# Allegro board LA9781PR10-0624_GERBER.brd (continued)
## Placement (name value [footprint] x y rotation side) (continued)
CD74  -  [C_0603]  151.74 45.85 270 bottom
CD75  -  [C_0603]  153.39 45.85 270 bottom
CD76  -  [C_0603]  157.45 45.85 270 bottom
CD77  -  [C_0603]  158.85 45.85 270 bottom
CD78  -  [C_0603]  162.79 45.85 270 bottom
CD79  -  [C_0603]  164.06 45.85 270 bottom
CD80  -  [C_SX]  179.04 84.27 0 top
CD81  -  [C_0402]  119.18 54.04 180 bottom
CD82  -  [C_0402]  119.18 53.15 180 bottom
CD83  -  [C_0402]  119.18 52.26 180 bottom
CD84  -  [C_0402]  119.18 51.37 180 bottom
CD85  -  [C_0402]  148.56 45.86 270 bottom
CD86  -  [C_0402]  147.55 45.86 270 bottom
CD87  -  [C_0402]  128.41 46.11 270 bottom
CD88  -  [C_0402]  127.52 46.11 270 bottom
CD89  -  [C_0402]  172.19 45.71 90 top
CD90  -  [C_0402]  144.58 83.63 180 top
CD91  -  [C_0402]  167.99 44.31 90 top
CD92  -  [C_0402]  209.9 89.9 90 top
CE1  -  [C_0402]  99.85 64.83 0 bottom
CE2  -  [C_0402]  100.73 57.6 0 bottom
CE3  -  [C_0402]  247.42 59.75 0 bottom
CE6  -  [C_0805]  125.58 113.56 270 bottom
CE8  -  [C_0402]  103.86 113.4 90 bottom
CE9  -  [C_0402]  100.81 113.4 90 bottom
CH2  -  [C_0402]  41.2 85.54 180 bottom
CH4  -  [C_0402]  65 55.89 270 top
CH5  -  [C_0402]  65 58.05 270 top
CH6  -  [C_0402]  68.53 54.14 90 top
CH7  -  [C_0402]  66.9 56.78 270 top
CH9  -  [C_0402]  79.98 52.77 270 bottom
CH10  -  [C_0402]  63.42 84.9 180 bottom
CH11  -  [C_0402]  63.55 48.32 180 top
CH12  -  [C_0402]  54.96 77.15 90 top
CH13  -  [C_0402]  89.92 73.01 0 bottom
CH14  -  [C_0402]  93.6 74.81 270 bottom
CH15  -  [C_0402]  87.98 59.75 0 top
CH16  -  [C_0402]  88.04 61.02 0 top
CH17  -  [C_0402]  62.28 78.68 180 bottom
CH18  -  [C_0402]  88.24 63.44 270 top
CH19  -  [C_0402]  86.21 62.8 270 top
CH20  -  [C_0603]  89.38 63.39 270 top
CH21  -  [C_0603]  75.03 76.26 90 top
CH22  -  [C_0402]  77.05 72.49 90 top
CH23  -  [C_0402]  74.64 71.05 270 top
CH24  -  [C_0402]  76.1 71.07 270 top
CH25  -  [C_0402]  76.1 68.32 270 top
CH26  -  [C_0603]  86.2 76.31 0 top
CH27  -  [C_0402]  79.34 64.7 270 top
CH28  -  [C_0805]  83.76 81.6 180 top
CH29  -  [C_0402]  76.1 63.85 90 top
CH30  -  [C_0402]  74.65 65.82 270 top
CH31  -  [C_0603]  76.81 76.96 270 top
CH32  -  [C_0603]  76.42 83.55 90 top
CH33  -  [C_0603]  74.7 83.55 90 top
CH34  -  [C_0402]  74.64 69.29 270 top
CH35  -  [C_0402]  79.34 65.57 90 top
CH36  -  [C_0402]  82.47 73.02 270 top
CH37  -  [C_0402]  77.93 69.3 90 top
CH38  -  [C_0603]  94.65 76.45 90 bottom
CH39  -  [C_0402]  73.1 66.82 270 top
CH40  -  [C_0402]  67.56 66.64 0 top
CH41  -  [C_0603]  81.76 75.95 90 top
CH42  -  [C_0402]  79.4 70.42 270 top
CH43  -  [C_0402]  76.1 65.63 90 top
CH44  -  [C_0402]  75.23 55.11 270 bottom
CH45  -  [C_0402]  77.75 66.27 90 top
CH46  -  [C_0402]  72.24 67.83 180 top
CH47  -  [C_0402]  85.83 65.6 90 top
CH48  -  [C_0402]  76.99 62.71 90 top
CH49  -  [C_0402]  73.07 69.99 90 top
CH50  -  [C_0402]  77.06 71.01 270 top
CH51  -  [C_0402]  79.6 55.82 90 top
CH52  -  [C_0603]  75.71 84.37 90 bottom
CH53  -  [C_0402]  69.26 62.42 90 top
CH54  -  [C_0402]  74.45 64.1 270 top
CH55  -  [C_0402]  71.22 52.77 270 bottom
CH56  -  [C_0402]  72.11 52.77 270 bottom
CH57  -  [C_0402]  73 52.77 270 bottom
CH58  -  [C_0402]  84.94 66.99 90 top
CH59  -  [C_0402]  73.07 68.19 90 top
CH60  -  [C_SX]  48.87 64.83 180 bottom
CH63  -  [C_0603]  90.67 76.47 90 bottom
CH64  -  [C_0402]  90.07 75.42 0 bottom
CH65  -  [C_0402]  81.13 70.17 90 top
CH66  -  [C_0402]  77.44 55.18 90 top
CH67  -  [C_0402]  80.93 68.51 270 top
CH68  -  [C_0402]  86.83 68.55 90 top
CH69  -  [C_0402]  79.4 67.35 90 top
CH70  -  [C_0402]  85.94 68.55 90 top
CH71  -  [C_0402]  81.93 67.87 0 top
CH72  -  [C_0402]  80.93 65.39 90 top
CH73  -  [C_0402]  77.88 63.73 90 top
CH74  -  [C_0402]  81.08 64.55 270 top
CH75  -  [C_0402]  80.49 59.5 180 top
CH76  -  [C_0402]  87.98 58.36 0 top
CH77  -  [C_0402]  92.56 56.58 0 bottom
CH78  -  [C_0402]  90.19 57.72 0 bottom
CH79  -  [C_0402]  88.95 54.93 180 top
CH80  -  [C_0402]  87.98 57.09 0 top
CH81  -  [C_0402]  68.43 71.51 270 top
CH82  -  [C_0402]  67.52 71.53 270 top
CH83  -  [C_0402]  66.65 71.51 270 top
CMOS1  -  [SHORTPADS]  68.93 56.58 270 top
D6  -  [BAT54CW_SOT323-3]  92.34 163.64 90 bottom
D7  -  [RB751VM-40TE-17_SOD323-2]  118.34 129.57 90 top
D8  -  [RB751VM-40TE-17_SOD323-2]  123.04 129.57 90 top
D14  -  [TVWDF1004AD0_DFN9]  290.15 112.29 180 bottom
D15  -  [L30ESDL5V0C3-2_SOT23-3]  296.77 122.01 0 bottom
D16  -  [TVWDF1004AD0_DFN9]  288.44 98.3 90 top
D17  -  [L30ESDL5V0C3-2_SOT23-3]  283.06 95 270 bottom
D18  -  [RB751VM-40TE-17_SOD323-2]  120.37 129.57 90 top
D19  -  [RB751VM-40TE-17_SOD323-2]  115.29 131.54 270 top
D28  -  [RB751S40T1_SOD523-2]  298.04 110.37 270 bottom
D31  -  [RB751V40_SC76-2]  119.99 155.05 90 bottom
D32  -  [RB751S40T1_SOD523-2]  120.43 131.2 0 bottom
D33  -  [L30ESD24VC3-2_SOT23-3]  121.39 111.42 180 bottom
D35  -  [RB751V40_SC76-2]  126.97 155.17 90 bottom
D36  -  [RB751V40_SC76-2]  136.07 171.39 180 top
D53  -  [RB751VM-40TE-17_SOD323-2]  93.79 164.53 0 bottom
D59  -  [RB751S40T1_SOD523-2]  33.5 85.98 270 top
D62  -  [RB751S40T1_SOD523-2]  34.9 85.98 270 top
D64  -  [RB751VM-40TE-17_SOD323-2]  100.18 162.08 90 bottom
D65  -  [RB751V40_SC76-2]  101.83 162.03 90 bottom
D66  -  [RB751VM-40TE-17_SOD323-2]  101.9 165.64 90 bottom
D68  -  [RB751VM-40TE-17_SOD323-2]  100.25 165.64 90 bottom
D69  -  [RB751VM-40TE-17_SOD323-2]  98.53 162.08 90 bottom
D71  -  [RB751VM-40TE-17_SOD323-2]  98.6 165.64 90 bottom
D73  -  [L30ESDL5V0C3-2_SOT23-3]  15.34 166.97 180 top
D90  -  [RB751S40T1_SOD523-2]  14.64 84.9 180 bottom
D91  -  [BAT1000-7-F_SOT23-3]  286.88 144.21 180 top
F3  -  [F_1206L150THWR]  290.49 141.4 90 top
FD1  -  [FIDUCIAL_C40M80]  12.67 161.86 0 top
FD2  -  [FIDUCIAL_C40M80]  10.64 161.99 180 bottom
FD3  -  [FIDUCIAL_C40M80]  290.55 14.03 0 top
FD4  -  [FIDUCIAL_C40M80]  290.55 14.03 180 bottom
H1  -  [H_3P0]  3.49 162.2 0 top
H2  -  [H_3P8]  33.69 75.9 0 top
H3  -  [H_3P0]  30.49 16.2 0 top
H4  -  [H_12P0X7P5]  48.39 32.2 180 top
H5  -  [H_3P0]  69.49 167.7 0 top
H6  -  [H_3P0]  141.69 146 0 top
H7  -  [H_3P8]  108.69 75.9 0 top
H8  -  [H_3P0]  117.49 77.2 0 top
H9  -  [H_3P0]  115.89 12.23 0 top
H10  -  [H_3P0]  123.29 7.43 0 top
H11  -  [H_3P0]  195.29 169.2 0 top
H12  -  [H_4P2]  151.67 144.99 0 top
H13  -  [H_4P2]  208.41 141.51 0 top
H14  -  [H_4P2]  149.69 104.2 0 top
H15  -  [H_4P2]  210.8 99.57 0 top
H16  -  [H_3P0]  215.49 90.5 0 top
H17  -  [H_3P6]  220.49 77.8 0 top
H18  -  [H_3P0]  198.39 26.03 0 top
H19  -  [H_3P6]  220.49 16.1 0 top
H20  -  [H_3P0]  270.89 87.13 0 top
H21  -  [H_3P0]  296.49 169.7 0 top
H22  -  [H_3P6X3P0]  293.29 159.2 0 top
H23  -  [H_3P6]  297.09 77.8 0 top
H24  -  [H_3P6]  297.09 16.1 0 top
H25  -  [H_3P0]  289.89 7.03 0 top
H26  -  [H_1P2]  73.09 157.9 0 top
H27  -  [H_1P2]  104.84 157.9 0 top
H28  -  [H_1P2]  136.59 157.9 0 top
JAPS1  -  [TYCO_1-2041070-6_16P]  14.09 120.44 270 bottom
JBT1  -  [ACES_50228-0127N-001_12P]  302.56 106.44 0 top
JCAM1  -  [ACES_50238-0207N-002_20P]  13.18 121.35 135 top
JCPU1  -  [INTEL_HASWELL_947P-T]  161.59 104.84 0 top
JCRT1  -  [SUYIN_070449HR015M221ZR_15P]  81.55 173.96 0 top
JDEG2  -  [ACES_87152-10071_10P]  275.84 31.09 270 bottom
JDIMM1  -  [TYCO_2-2013310-1_204P]  189.24 72.25 0 top
JDIMM2  -  [TYCO_2-2013289-1_204P]  189.24 64.05 0 bottom
JDIMM3  -  [TYCO_2-2013289-1_204P]  189.24 58.05 0 top
JDIMM4  -  [TYCO_2-2013290-1_204P]  189.24 49.85 0 bottom
JDOCK1  -  [JAE_WD2F144WB5R400_144P]  81.74 118.7 0 bottom
JDP1  -  [FOX_3V11211-NBYD7-7H_20P]  293.78 150.25 90 top
JEDP1  -  [ACES_50398-04071-001_40P]  130.49 156.27 0 top
JESA1  -  [TAIWI_EU093-117CRL-TW_11P]  14.49 170.97 180 top
JFAN1  -  [ACES_50271-0040N-001_4P]  226.23 80.15 315 bottom
JFAN2  -  [ACES_50271-0040N-001_4P]  11.15 87.44 90 bottom
JHDMI1  -  [CONCR_099AAAC19BBLCNF_19P]  27.94 168.64 180 top
JIO1  -  [FOX_QTSA1401-7011-9H_140P-T]  14.14 102.9 90 top
JKB1  -  [E-T_6900K-G10N-40R_10P]  131.5 103.62 0 top
JLOM1  -  [SANTA_130454-H_13P]  52.22 162.27 180 top
JLVDS1  -  [ACES_50398-04071-001_40P]  98.74 156.27 0 top
JMINI1  -  [LCN_DAN08-52526-0100_52P]  269.69 65 270 bottom
JMINI2  -  [LCN_DAN08-52526-0100_52P]  110.69 168 0 bottom
JMINI3  -  [LCN_DAN08-52526-0100_52P]  90.54 20.35 180 bottom
JMINI4  -  [LCN_DAN08-52526-0100_52P]  9.64 157.75 0 bottom
JMXM1  -  [JAE_MM70-314-310B1-1-R3_310P-S]  31.19 136.7 0 top
JODD1  -  [OCTEK_SLS-13SZAB_13P]  24.26 41.63 270 top
JPB1  -  [ACES_50228-0067N-001_6P]  276.49 90.98 180 top
JRTC1  -  [ACES_50271-0020N-001_2P]  51.89 99.82 270 bottom
JSATA1  -  [OCTEK_SAT-22PDAB_22P]  200.43 35.91 90 top
JSATA2  -  [OCTEK_SAT-22PDAB_22P]  63.98 32.2 0 top
JSIM1  -  [T-SOL_159-1000302602_10P-T]  263.44 19.03 180 bottom
JSPI1  -  [TYCO_2-2041070-0_20P-T]  111.53 50.74 0 bottom
JTAG1  -  [SHORTPADS]  251.43 38.04 0 bottom
JUSB1  -  [LOTES_AUSB0041-P002A_9P]  293.26 116.34 90 top
JUSB2  -  [LOTES_AUSB0041-P002A_9P]  293.26 93.25 90 top
JUSH1  -  [E-T_6700K-Y20N-00L_20P]  114.91 36.82 90 top
JWL1  -  [ACES_50228-0034N-001_3P]  283.62 7.24 180 top
JXDP1  -  [ACES_50559-02601-001_26P-T]  207.99 128.44 270 top
JXDP2  -  [SAMTE_BSH-030-01-L-D-A_60P]  43.63 74.95 90 bottom
L1  -  [MURAT_BLM15BB470SN1D_2P]  80.11 160.72 180 bottom
L2  -  [MURAT_BLM15BB470SN1D_2P]  86.59 161.06 90 bottom
L3  -  [MURAT_BLM15BB470SN1D_2P]  88.49 161.01 90 bottom
L4  -  [MURAT_BLM15AG121SN1D_L0402_2P]  86.11 165.42 0 top
L5  -  [MURAT_BLM15AG121SN1D_L0402_2P]  89.73 165.42 180 top
L10  -  [MURAT_DLW21SN121SQ2L_4P]  31.62 127.5 180 top
L11  -  [MURAT_DLW21SN121SQ2L_4P]  31.53 115.32 180 top
L19  -  [MURAT_DLW21SN900HQ2L_0805_4P]  36.59 162.92 90 top
L23  -  [MURAT_DLW21SN900HQ2L_0805_4P]  33.04 162.92 90 top
L24  -  [MURAT_DLW21SN900HQ2L_0805_4P]  29.48 162.92 90 top
L25  -  [MURAT_DLW21SN900HQ2L_0805_4P]  26.18 162.92 90 top
L29  -  [TAIYO_CBC2012T4R7M_2P]  107.29 85.55 90 bottom
L39  -  [MURAT_DLW21SN900SQ2L_0805_4P]  297.2 117.75 270 bottom
L40  -  [MURAT_DLW21SN900HQ2L_0805_4P]  288.56 110.39 270 bottom
L41  -  [CHENG_OCE2012120YZF_4P]  278.09 90.28 270 bottom
L42  -  [MURAT_DLW21SN900HQ2L_0805_4P]  290.59 110.39 270 bottom
L43  -  [MURAT_DLW21SN900HQ2L_0805_4P]  285.02 100.08 180 top
L44  -  [MURAT_DLW21SN900HQ2L_0805_4P]  285.04 97.75 180 top
L51  -  [MURAT_DLW21SN900SQ2L_0805_4P]  15.77 161.14 90 top
L60  -  [KC_FBMA-L11-201209-221LMA30_2P]  117.89 140.15 180 bottom
L61  -  [KC_FBMA-L11-201209-221LMA30_2P]  129.07 147 0 top
L62  -  [CYNTE_PG031B-4R7MS_2P]  127.06 138.88 180 bottom
L63  -  [DELTA_0603CS-120EJTS_2P]  105.54 97.62 90 top
L64  -  [DELTA_0603CS-120EJTS_2P]  107.02 97.62 90 top
L65  -  [DELTA_0603CS-120EJTS_2P]  108.51 97.62 90 top
L66  -  [DELTA_0603CS-120EJTS_2P]  109.98 97.62 90 top
L67  -  [DELTA_0603CS-120EJTS_2P]  111.47 97.62 90 top
L68  -  [DELTA_0603CS-120EJTS_2P]  112.94 97.62 90 top
L69  -  [DELTA_0603CS-120EJTS_2P]  114.41 97.62 90 top
L70  -  [DELTA_0603CS-120EJTS_2P]  115.89 97.62 90 top
LH1  -  [MURAT_BLM18PG181SN1D_2P]  90.78 62.17 90 top
LH2  -  [MURAT_LQM18FN4R7M00D_2P]  92.05 77.8 270 bottom
ME1  -  [SHORTPADS]  69.61 54.34 90 top
NOREF  -  []  149.69 104.2 0 top
NOREF#2  -  []  129.45 36.96 0 top
NOREF#3  -  []  1.14 247.18 0 top
NOREF#4  -  []  127.35 85.73 0 top
NOREF#5  -  []  84.92 -59.26 0 top
NOREF#6  -  []  125.45 172.56 0 top
NOREF#7  -  []  210.8 99.57 0 top
NOREF#8  -  []  208.41 141.51 0 top
NOREF#9  -  []  195.29 169.2 0 top
NOREF#10  -  []  139.67 134.05 0 top
NOREF#11  -  []  151.67 144.99 0 top
NOREF#12  -  []  129.26 81.2 0 top
NOREF#13  -  []  146.02 173.1 180 bottom
NOREF#14  -  []  189.97 172.94 180 bottom
NOREF#15  -  []  189.14 95.5 180 bottom
PBATT1  -  [SUYIN_200045GR009M28QZR_9P]  189.34 2.65 0 top
PC1  -  [C_EEEFK1E101YP]  14.87 111.44 0 top
PC2  -  [C_0603]  50.58 103.7 180 bottom
PC4  -  [C_0402]  192.92 6.53 0 top
PC5  -  [C_0402]  202.25 9.34 180 top
PC6  -  [C_0402]  6.32 136.03 270 bottom
PC7  -  [C_0603]  40.47 84.7 0 top
PC8  -  [C_0603]  40.97 77.57 180 top
PC9  -  [C_0603]  25.35 63.35 180 top
PC11  -  [C_0402]  22.53 77.43 90 bottom
PC14  -  [C_0805]  7.76 74.49 0 top
PC15  -  [C_0603]  4.8 84.84 90 top
PC16  -  [C_0402]  42.92 86.2 90 top
PC17  -  [C_0402]  1.8 138.62 0 bottom
PC18  -  [C_0402]  11.64 135.89 0 top
PC19  -  [C_0402]  8.18 138.24 180 bottom
PC20  -  [C_0402]  2.97 135.45 180 top
PC21  -  [C_0402]  11.64 136.78 0 top
PC30  -  [C_0805]  17.66 116.02 0 top
PC31  -  [C_0603]  17.82 117.54 0 top
PC101  -  [C_APXK6R3ARA221MF451]  47.83 43.75 180 bottom
PC102  -  [C_APXK6R3ARA221MF451]  37.81 21.66 90 bottom
PC104  -  [C_0805]  36.95 31.45 180 top
PC105  -  [C_0402]  28.98 49.57 180 top
PC106  -  [C_0402]  28.98 50.46 180 top
PC109  -  [C_0805]  30.25 49.99 0 top
PC110  -  [C_0805]  36.92 29.64 180 top
PC111  -  [C_0603]  35.32 33.78 180 bottom
PC112  -  [C_0603]  36.13 41.4 90 bottom
PC114  -  [C_0603]  31.36 38.32 0 bottom
PC116  -  [C_0603]  38.43 50.53 180 top
PC117  -  [C_0603]  39.26 38.58 0 bottom
PC118  -  [C_0603]  39.25 37.36 0 bottom
PC119  -  [C_0603]  31.52 30.04 0 top
PC120  -  [C_0603]  29.17 40.04 180 bottom
PC199  -  [C_0402]  39.7 40.3 0 bottom
PC201  -  [C_APXK2R5ARA331MF451]  113.01 26.19 0 bottom
PC202  -  [C_0805]  139.6 24.31 270 bottom
PC203  -  [C_0805]  141.5 24.34 270 bottom
PC204  -  [C_0402]  142.82 23.74 270 bottom
PC205  -  [C_0402]  143.71 23.74 270 bottom
PC206  -  [C_0603]  147.66 19.33 180 bottom
PC207  -  [C_0805]  147.46 25.84 0 bottom
PC208  -  [C_0805]  147.44 27.61 0 bottom
PC209  -  [C_0402]  150.34 25.64 90 bottom
PC210  -  [C_0603]  152.12 19.56 270 bottom
PC211  -  [C_0402]  152.58 26.56 180 bottom
PC212  -  [C_0603]  138.89 18.19 90 top
PC213  -  [C_0603]  150.86 19.02 270 bottom
PC214  -  [C_0402]  151.67 27.54 0 bottom
PC215  -  [C_0402]  153.64 18.68 270 bottom
PC216  -  [C_0402]  160.41 19.79 0 bottom
PC217  -  [C_0402]  156.69 24.78 180 bottom
PC219  -  [C_0402]  160.33 24.78 180 bottom
PC220  -  [C_0402]  157.38 20.05 0 bottom
PC301  -  [C_APXK2R5ARA331MF451]  47.1 50.78 0 bottom
PC302  -  [C_0402]  35.42 57.49 90 top
PC303  -  [C_0402]  34.4 57.49 90 top
PC304  -  [C_0805]  34.68 55.21 270 top
PC305  -  [C_0805]  36.43 55.18 270 top
PC306  -  [C_0603]  39.98 62.39 270 top
PC307  -  [C_0402]  39.79 71.2 270 bottom
PC308  -  [C_0603]  39.6 63.56 90 top
PC309  -  [C_0402]  44.76 53.09 180 top
PC400  -  [C_0805]  107.5 32.66 270 bottom
PC402  -  [C_0402]  102 33.33 270 bottom
PC403  -  [C_0805]  102.21 21.32 270 bottom
PC404  -  [C_0805]  104 21.32 270 bottom
PC406  -  [C_0402]  102.59 30 90 bottom
PC407  -  [C_0402]  99.39 25.02 270 bottom
PC500  -  [C_0603]  202.06 172.18 0 top
PC501  -  [C_0603]  199.07 173.58 270 top
PC502  -  [C_0805]  198.98 163.73 270 bottom
PC503  -  [C_0805]  183.49 165.67 0 top
PC504  -  [C_0805]  170.98 165.68 0 top
PC507  -  [C_0603]  197.2 155.58 90 bottom
PC508  -  [C_0603]  157.86 168.21 270 bottom
PC509  -  [C_0402]  156.65 174.48 270 top
PC510  -  [C_0402]  155.7 175.4 0 top
PC511  -  [C_0603]  155.68 166.5 90 bottom
PC512  -  [C_0805]  176.82 165.68 0 bottom
PC513  -  [C_0805]  203.08 165.42 0 bottom
PC514  -  [C_0805]  192.12 164.11 270 bottom
PC515  -  [C_0402]  166.34 164.73 270 top
PC516  -  [C_0402]  165.45 164.73 270 top
PC519  -  [C_0603]  153.64 165.99 90 bottom
PC520  -  [C_0402]  147.29 172.07 90 top
PC521  -  [C_0603]  162.09 165.67 180 top
PC522  -  [C_0402]  151.23 169.69 270 bottom
PC523  -  [C_0603]  187.46 158.21 0 bottom
PC525  -  [C_0402]  150.5 173.88 0 top
PC526  -  [C_0402]  148.51 174.01 0 top
PC527  -  [C_0402]  148.56 174.86 0 bottom
PC528  -  [C_0402]  150.39 167.32 0 top
PC529  -  [C_EEEFK1E101YP]  180.57 168.38 90 top
PC530  -  [C_EEEFK1E101YP]  173.46 168.38 90 top
PC531  -  [C_EEEFK1E101YP]  187.55 168.38 90 top
PC532  -  [C_0603]  149.9 164.91 0 bottom
PC533  -  [C_0805]  203.05 165.42 0 top
PC534  -  [C_0805]  176.82 165.68 0 top
PC535  -  [C_0805]  192.12 164.11 270 top
PC538  -  [C_0603]  149.9 166.18 0 top
PC539  -  [C_0402]  148.59 165.59 180 top
PC540  -  [C_0603]  156.31 162.81 90 top
PC541  -  [C_0402]  148.66 166.48 180 top
PC542  -  [C_0402]  149.5 169.3 0 top
PC543  -  [C_0402]  148.69 167.37 180 top
PC544  -  [C_0402]  151.31 170.19 270 top
PC545  -  [C_0603]  168.2 157.04 180 top
PC546  -  [C_0402]  154.68 169.61 180 bottom
PC547  -  [C_0402]  153.69 168.59 0 bottom
PC700  -  [C_0603]  30.44 68.74 0 top
PC701  -  [C_0603]  51.4 38.46 90 top
PC702  -  [C_0402]  227.96 33.64 180 bottom
PC703  -  [C_0402]  226.95 32.63 180 bottom
PC704  -  [C_0402]  226.06 33.64 180 bottom
PC705  -  [C_0402]  220.32 31.99 90 bottom
PC706  -  [C_0603]  215.62 33.15 90 bottom
PC707  -  [C_0805]  217.14 32.11 90 bottom
PC708  -  [C_0805]  218.92 32.11 90 bottom
PC715  -  [C_0805]  198.65 17.68 90 bottom
PC717  -  [C_0402]  216.48 19.5 180 bottom
PC718  -  [C_0805]  196.92 17.68 90 bottom
PC719  -  [C_0805]  200.38 17.68 90 bottom
PC727  -  [C_0402]  228.4 20.51 180 bottom
PC728  -  [C_0402]  228.4 21.4 180 bottom
PC729  -  [C_0402]  237.36 15.41 270 bottom
PC730  -  [C_0402]  238.24 16.27 90 bottom
PC731  -  [C_0402]  230.81 16.45 180 bottom
PC732  -  [C_0402]  228.4 17.59 180 bottom
PC733  -  [C_0402]  243.99 20.26 0 bottom
PC734  -  [C_0603]  223.18 29.66 180 bottom
PC735  -  [C_0402]  228.4 19.5 180 bottom
PC736  -  [C_0402]  237.34 21.2 90 bottom
PC744  -  [C_0402]  231.37 31.51 270 bottom
PC745  -  [C_0603]  224.93 25.01 270 bottom
PC746  -  [C_0402]  229.61 49.09 270 bottom
PC783  -  [C_0402]  231.37 32.88 90 bottom
PC786  -  [C_0603]  229.15 23.76 90 bottom
PC791  -  [C_0603]  224.06 30.93 180 bottom
PC792  -  [C_0603]  227.24 22.54 0 bottom
PC900  -  [C_0805]  183.74 126.68 270 top
PC901  -  [C_0805]  189.08 126.68 270 top
PC902  -  [C_0805]  187.3 126.68 270 top
PC903  -  [C_0805]  185.52 126.68 270 top
PC904  -  [C_0805]  180.06 126.56 270 top
PC905  -  [C_D2]  182.09 121.78 180 top
PC906  -  [C_D2]  193.09 149.63 90 bottom
PC907  -  [C_D2]  178.54 149.66 90 bottom
PC908  -  [C_D2]  183.36 149.66 90 bottom
PC909  -  [C_0805]  178.28 126.56 270 top
PC910  -  [C_0805]  176.5 126.56 270 top
PC911  -  [C_0805]  174.73 126.56 270 top
PC912  -  [C_0805]  172.95 126.56 270 top
PC913  -  [C_0805]  171.17 126.56 270 top
PC914  -  [C_0805]  169.39 126.56 270 top
PC915  -  [C_D2]  188.24 149.66 90 bottom
PC916  -  [C_D2]  182.09 121.78 180 bottom
PC917  -  [C_0805]  169.39 126.56 270 bottom
PC918  -  [C_0805]  171.17 126.56 270 bottom
PC919  -  [C_0805]  172.95 126.56 270 bottom
PC920  -  [C_0805]  174.73 126.56 270 bottom
PC921  -  [C_0805]  176.5 126.56 270 bottom
PC922  -  [C_0805]  178.28 126.56 270 bottom
PC923  -  [C_0805]  180.06 126.56 270 bottom
PC924  -  [C_0805]  183.74 126.68 270 bottom
PC925  -  [C_0805]  186.19 146.75 0 top
PC926  -  [C_0805]  189.11 146.75 0 top
PC935  -  [C_0805]  181.04 146.75 180 top
PC936  -  [C_0805]  178.12 146.75 180 top
PC937  -  [C_0805]  185.52 126.68 270 bottom
PC938  -  [C_0805]  187.3 126.68 270 bottom
PC939  -  [C_0805]  189.08 126.68 270 bottom
PC940  -  [C_0805]  178.12 146.75 180 bottom
PC941  -  [C_0805]  181.04 146.75 180 bottom
PC942  -  [C_0805]  186.19 146.75 0 bottom
PC943  -  [C_0805]  189.11 146.75 0 bottom
PC1001  -  [C_0805]  131.79 113.6 270 top
PC1002  -  [C_0402]  174.67 25.34 180 bottom
PC1003  -  [C_0402]  174.66 24.32 180 bottom
PC1004  -  [C_0603]  184.52 15.81 180 bottom
PC1005  -  [C_0603]  191.1 23.24 0 bottom
PC1006  -  [C_0603]  264.01 25.91 270 bottom
PC1007  -  [C_0603]  262.61 25.91 270 bottom
PC1008  -  [C_0603]  256.45 29.53 180 bottom
PC1009  -  [C_0402]  256.46 30.67 180 bottom
PC1080  -  [C_0402]  220.95 60.69 90 bottom
PC1081  -  [C_0402]  221.13 53.02 0 bottom
PC1099  -  [C_0603]  175.1 28.87 270 top
PD1  -  [BAS40CW_SOT323-3]  50.62 101.7 270 bottom
PD2  -  [TVNST52302AB0_SOT523-3]  197.93 8.31 270 top
PD3  -  [TVNST52302AB0_SOT523-3]  200.42 8.32 270 top
PD5  -  [SDMK0340L-7-F_SOD323-2]  208.13 8.99 270 top
PD8  -  [D_0603]  21.1 78.3 90 bottom
PD700  -  [SBR3A40SA-13_SMA2]  2.98 67.31 90 top
PD701  -  [BAT54CW_SOT323-3]  223.37 36.16 270 bottom
PD703  -  [SDMK0340L-7-F_SOD323-2]  222.73 26.28 270 bottom
PD1001  -  [PDS5100H-13_POWERDI5-3]  122.04 110.48 90 top
PD1002  -  [PDS5100H-13_POWERDI5-3]  181.01 24.83 0 bottom
PD1010  -  [BAT54CW_SOT323-3]  250.34 15.22 90 bottom
PD1099  -  [SDMK0340L-7-F_SOD323-2]  160.05 21.4 180 top
PD1100  -  [SDMK0340L-7-F_SOD323-2]  251.99 17.28 270 bottom
PH500  -  [R_0402]  164.79 161.35 0 top
PH501  -  [R_0402]  169.09 155.21 270 top
PJP3  -  [JUMP_43X79]  90.48 36.51 0 top
PJP9  -  [JUMP_43X39]  2.13 144.59 90 top
PJP29  -  [JUMP_43X39]  247.32 74.87 180 bottom
PJP30  -  [JUMP_43X79]  296.39 57.09 270 bottom
PJP31  -  [JUMP_43X79]  18.77 157.04 270 top
PJP34  -  [JUMP_43X39]  261.34 78.73 90 bottom
PJP65  -  [JUMP_43X39]  253.03 54.55 180 bottom
PJP77  -  [JUMP_43X39]  259.31 56.83 180 bottom
PJP78  -  [JUMP_43X118]  22.92 132.4 0 top
PJP79  -  [JUMP_43X118]  22.92 137.61 0 top
PJP82  -  [JUMP_43X118]  58.65 21.7 270 bottom
PJP89  -  [JUMP_43X79]  77.36 38.67 180 top
PJP90  -  [JUMP_43X79]  107.42 42.52 270 top
PJP91  -  [JUMP_43X79]  66.61 39.94 0 top
PJP92  -  [JUMP_43X79]  107.16 166.77 90 top
PJP93  -  [JUMP_43X79]  41.88 132.57 270 top
PJP94  -  [JUMP_43X79]  108.35 37.66 180 top
PJP100  -  [JUMP_43X118]  52.68 45.81 90 bottom
PJP101  -  [JUMP_43X118]  52.81 41.87 0 bottom
PJP102  -  [JUMP_43X118]  49.72 20 0 bottom
PJP103  -  [JUMP_43X118]  49.72 14.54 0 bottom
PJP200  -  [JUMP_43X118]  141.37 26.38 90 bottom
PJP201  -  [JUMP_43X39]  145.29 23.69 0 bottom
PJP202  -  [JUMP_43X39]  147.59 30.09 270 bottom
PJP203  -  [JUMP_43X118]  122.45 23.97 270 bottom
PJP204  -  [JUMP_43X118]  127.66 23.97 270 bottom
PJP300  -  [JUMP_43X79]  31.54 57.9 0 top
PJP301  -  [JUMP_43X79]  51.68 52.92 270 bottom
PJP302  -  [JUMP_43X79]  55.5 52.93 270 bottom
PJP400  -  [JUMP_43X79]  110.3 32.29 270 bottom
PJP401  -  [JUMP_43X79]  99.07 20 0 bottom
PJPDC1  -  [ACES_50493-0110N-001_11P]  15.85 61.78 90 bottom
PL1  -  [CHT_C8BBPH853025_2P]  7.03 111.37 0 top
PL2  -  [TAIYO_FBMJ4516HS720NT_2P]  191.43 9.84 180 top
PL3  -  [MURAT_BLM15HG601SN1D_2P]  8.36 91.98 270 top
PL4  -  [CHT_C8BBPH853025_2P]  9.12 80.58 90 top
PL6  -  [TAIYO_FBMJ4516HS720NT_2P]  191.43 7.4 180 top
PL100  -  [CYNTE_PCMB053T-1R0MS_2P]  30.39 56.7 90 bottom
PL102  -  [TOKO_FDV0630-3R3M-P3_2P]  30.44 29.05 270 bottom
PL103  -  [TOKO_FDSD0630-H-2R2M-P3_2P]  30.45 47.05 0 bottom
PL201  -  [CYNTE_PCMC104T-1R0MN_2P]  124.77 16.31 0 top
PL301  -  [TAI-T_VMPI0703AR-4R7M-Z01_2P]  37.84 57.8 0 bottom
PL401  -  [CYNTE_PH041H-1R0MS_2P]  102.59 26.51 270 bottom
PL500  -  [NEC_MPC0740LR42C_2P]  193.44 149.08 90 top
PL501  -  [NEC_MPC0740LR42C_2P]  183.62 149.24 90 top
PL502  -  [NEC_MPC0740LR42C_2P]  173.71 149.49 90 top
PL510  -  [L_1812-1806]  166.85 167.35 90 top
PL700  -  [CYNTE_PCMB053T-1R0MS_2P]  210.94 31.08 180 bottom
PL701  -  [CYNTE_PCMB104T-5R6MS_2P]  208.58 25.92 270 bottom
PQ1  -  [NTR4502PT1G_SOT23-3]  205.99 7.94 90 top
PQ2  -  [FDV301N_NL_SOT23-3]  8.36 93.89 0 top
PQ3  -  [MMST3904-7-F_SOT323-3]  11.53 96.14 180 top
PQ4  -  [TP0610K-T1-E3_SOT23-3]  40.97 79.97 0 top
PQ5  -  [SI7447DP_SO8_5P]  6.07 81.45 180 top
PQ7  -  [SSM3K7002FU_SC70-3]  39.79 86.55 270 top
PQ8  -  [IMD2AT-108_SC74-6]  22.75 59.01 270 top
PQ101  -  [SIS412DN-T1-GE3_POWERPAK8-5]  32.6 46.32 90 top
PQ102  -  [SIS412DN-T1-GE3_POWERPAK8-5]  33.92 27.91 270 top
PQ103  -  [SI7716ADN-T1-GE3_POWERPAK8-5]  36.18 48.97 180 top
PQ104  -  [SI7716ADN-T1-GE3_POWERPAK8-5]  35.12 32.31 0 bottom
PQ201  -  [SIR472DP-T1-GE3_POWERPAK8-5]  132.18 23.59 90 bottom
PQ202  -  [SIR472DP-T1-GE3_POWERPAK8-5]  137.68 21.7 270 bottom
PQ204  -  [DMN66D0LDW-7_SOT363-6]  161.12 21.4 180 bottom
PQ205  -  [DMN66D0LDW-7_SOT363-6]  158 21.54 180 bottom
PQ301  -  [SIS412DN-T1-GE3_POWERPAK8-5]  38.73 59.44 180 top
PQ303  -  [SI7716ADN-T1-GE3_POWERPAK8-5]  40.4 54.09 0 top
PQ323  -  [DMN65D8LW-7_SOT323-3]  2.39 140.33 0 top
PQ500  -  [CSD86350Q5D_SON8]  197.64 163.79 180 top
PQ501  -  [CSD86350Q5D_SON8]  203.57 163.77 180 top
PQ502  -  [CSD86350Q5D_SON8]  183.54 164.05 180 top
PQ503  -  [CSD86350Q5D_SON8]  189.72 164.07 180 top
PQ504  -  [CSD86350Q5D_SON8]  177.19 164.05 180 top
PQ505  -  [CSD86350Q5D_SON8]  171.07 164.07 180 top
PQ700  -  [NTR4502PT1G_SOT23-3]  33.12 62.17 90 top
PQ701  -  [SI7447DP_SO8_5P]  5.61 66.03 0 top
PQ702  -  [NTR4502PT1G_SOT23-3]  32.99 66.1 90 top
PQ703  -  [NTGD4161PT1G_TSOP6]  127.16 133.32 180 top
PQ704  -  [SIR472DP-T1-GE3_POWERPAK8-5]  214.6 26.81 90 bottom
PQ705  -  [FDMC7692S_MLP8-5]  217.34 25.09 270 bottom
PQ706  -  [DMN66D0LDW-7_SOT363-6]  238.72 20.64 90 bottom
PQ707  -  [DMN66D0LDW-7_SOT363-6]  253.37 14.57 90 bottom
PQ708  -  [DMN66D0LDW-7_SOT363-6]  234.56 16.27 270 bottom
PQ1001  -  [SI7447DP_SO8_5P]  125.19 109.82 0 top
PQ1002  -  [SI4835DDY-T1-E3_SO8]  185.93 15.69 270 top
PQ1003  -  [SI7447DP_SO8_5P]  191.59 15.09 180 bottom
PQ1004  -  [SI7447DP_SO8_5P]  179.23 17.84 90 bottom
PQ1005  -  [SI4835DDY-T1-E3_SO8]  185.93 21.27 270 top
PQ1008  -  [SI7447DP_SO8_5P]  168.82 18.1 90 top
PQ1009  -  [SI7447DP_SO8_5P]  171.36 21.91 270 top
PQ1010  -  [SSM3K7002FU_SC70-3]  172.57 26.17 0 top
PQ1011  -  [SSM3K7002FU_SC70-3]  250.45 17.62 270 bottom
PQ1070  -  [NTR4502PT1G_SOT23-3]  255.5 18.07 180 bottom
PQ1071  -  [DMN66D0LDW-7_SOT363-6]  251.22 19.67 180 bottom
PQ1072  -  [NTR4502PT1G_SOT23-3]  245.87 17.37 0 bottom
PQ1080  -  [DMN66D0LDW-7_SOT363-6]  222.48 47.07 180 bottom
PQ1082  -  [SSM3K7002FU_SC70-3]  224.51 49.4 0 bottom
PQ1083  -  [IMD2AT-108_SC74-6]  241.24 16.28 180 bottom
PR1  -  [R_0402]  50.09 99.89 180 bottom
PR2  -  [R_0402]  209.65 9.18 0 top
PR3  -  [RP_0804_8P4R]  193.91 7.87 90 top
PR7  -  [R_0402]  6.7 91.94 90 top
PR8  -  [R_0402]  8.53 97.85 0 top
PR9  -  [R_0402]  6.76 97.85 0 top
PR10  -  [R_0402]  10.01 92.85 270 top
PR11  -  [R_0402]  11.02 99.76 0 top
PR12  -  [R_0402]  10.9 91.94 90 top
PR13  -  [R_0402]  11.61 97.73 180 top
PR14  -  [R_0402]  8.18 135.19 180 bottom
PR15  -  [R_0402]  38.57 84.56 0 top
PR16  -  [R_0402]  23.95 62.27 0 top
PR17  -  [R_0402]  38.57 85.43 0 top
PR18  -  [R_0402]  8.66 73.09 0 top
PR19  -  [R_0805]  6.32 84.68 90 top
PR20  -  [R_0402]  25.81 62.27 0 top
PR21  -  [R_0402]  42.88 84.06 90 top
PR22  -  [R_0402]  26.89 60.18 270 top
PR23  -  [R_0402]  43.9 84.01 90 top
PR24  -  [R_0402]  8.18 136.08 180 bottom
PR25  -  [R_1206_4P-D]  9.88 138.2 270 bottom
PR26  -  [R_0402]  2.97 134.56 180 top
PR27  -  [R_0402]  2.06 133.67 0 top
PR28  -  [R_0402]  7.26 137.35 0 bottom
PR29  -  [R_0402]  2.06 136.46 0 top
PR30  -  [R_0402]  2.39 141.42 90 top
PR31  -  [R_0402]  2.97 137.35 180 top
PR33  -  [R0402_0OHM]  201.33 8.45 0 top
PR100  -  [R_0402]  31.12 40.58 270 bottom
PR101  -  [R_0402]  31.06 35.19 90 bottom
PR102  -  [R_0402]  32.01 40.5 270 bottom
PR103  -  [R0402_0OHM]  32.53 37.25 180 bottom
PR104  -  [R_0402]  31.95 35.12 90 bottom
PR105  -  [R_0402]  32.96 39.61 90 bottom
PR106  -  [R_0402]  32.89 36.03 270 bottom
PR107  -  [R_0603]  37.68 33.78 180 bottom
PR108  -  [R_0603]  37.5 42.88 270 bottom
PR109  -  [R_1206]  38.16 46.19 90 top
PR110  -  [R_1206]  32.17 26.01 90 top
PR111  -  [R0402_0OHM]  29.61 41.44 180 bottom
PR112  -  [R_0402]  29.44 42.71 180 bottom
PR118  -  [R0402_0OHM]  34.8 42.43 270 bottom
PR119  -  [R_0402]  33.85 41.57 90 bottom
PR200  -  [R_0603]  146.02 20.7 90 bottom
PR201  -  [R_0402]  148.8 18.86 0 bottom
PR202  -  [R_1206]  138.31 14.02 90 top
PR203  -  [R_0603]  147.97 17.65 0 bottom
PR204  -  [R_0402]  151.66 25.59 0 bottom
PR205  -  [R_0402]  154.38 21.91 180 bottom
PR206  -  [R_0402]  154.53 17.77 90 bottom
PR207  -  [R_0402]  154.43 25.59 180 bottom
PR208  -  [R_0402]  154.38 22.79 180 bottom
PR209  -  [R_0402]  154.46 20.89 180 bottom
PR211  -  [R_0402]  162.26 24.86 90 bottom
PR213  -  [R_0402]  159.46 19.06 90 bottom
PR216  -  [R_0402]  159.85 26.99 0 bottom
PR217  -  [R_0402]  160.41 18.74 0 bottom
PR218  -  [R_0402]  158.45 25.72 270 bottom
PR219  -  [R_0402]  161.25 25.69 270 bottom
PR220  -  [R_0402]  160.35 25.84 180 bottom
PR221  -  [R_0402]  156.54 19.17 90 bottom
PR222  -  [R_0402]  155.76 26.74 0 bottom
PR223  -  [R_0402]  157.56 25.69 270 bottom
PR224  -  [R_0402]  157.38 19.12 0 bottom
PR225  -  [R_0402]  156.67 25.72 180 bottom
PR240  -  [R0402_0OHM]  155.42 18.68 270 bottom
PR300  -  [R_0402]  37.57 68.19 90 bottom
PR301  -  [R_0603]  37.72 62.39 270 top
PR302  -  [R_0402]  38.58 65.9 90 top
PR303  -  [R_0402]  61.7 56.88 180 top
PR304  -  [R_1206]  44.34 57 270 top
PR305  -  [R_0402]  40.56 66.9 270 top
PR306  -  [R_0402]  39.22 69.1 270 bottom
PR307  -  [R_0402]  40.11 69.1 270 bottom
PR315  -  [R0402_0OHM]  60.78 56.01 0 top
PR400  -  [R_0402]  101.42 28.8 0 bottom
PR401  -  [R_0603]  99.25 27.39 270 bottom
PR402  -  [R_0402]  101.12 33.33 270 bottom
PR403  -  [R_0402]  99.92 30.91 270 bottom
PR404  -  [R_0402]  100.81 30 90 bottom
PR405  -  [R_0402]  100.1 32.41 90 bottom
PR406  -  [R0402_0OHM]  101.7 30.91 270 bottom
PR500  -  [R_0402]  160.68 170.75 0 bottom
PR501  -  [R0402_0OHM]  201 172.72 180 top
PR502  -  [R_0603]  200.72 170.54 0 bottom
PR503  -  [R_0402]  160.68 171.64 0 bottom
PR504  -  [R_0402]  160.68 172.53 0 bottom
PR505  -  [R0402_0OHM]  161.59 170.75 180 top
PR506  -  [R0402_0OHM]  161.59 171.64 180 top
PR507  -  [R_0402]  161.59 168.09 180 top
PR508  -  [R0402_0OHM]  161.59 172.53 180 top
PR509  -  [R_0402]  161.59 168.97 180 top
PR510  -  [R_0603]  156.08 160.5 270 top
PR511  -  [R_0603]  157.43 160.5 270 top
PR512  -  [R_0402]  158.49 160.26 270 top
PR513  -  [R0402_0OHM]  159.36 174.36 270 top
PR514  -  [R_0402]  161.59 169.86 180 top
PR515  -  [R_1206]  197.2 158.56 180 bottom
PR516  -  [R_0402]  159.43 160.26 270 top
PR517  -  [R_0402]  160.24 174.33 270 top
PR518  -  [R_0402]  160.32 160.26 270 top
PR519  -  [R_0402]  158.67 175.32 0 top
PR520  -  [R0603_0OHM]  158.85 164.21 270 top
PR521  -  [R_0402]  157.58 173.55 90 top
PR522  -  [R0402_0OHM]  158.47 174.38 270 top
PR523  -  [R_0402]  159.92 164.28 0 top
PR524  -  [R0402_0OHM]  155.67 174.54 270 top
PR525  -  [R_0402]  153.77 173.62 90 top
PR526  -  [R0402_0OHM]  153.77 164.28 270 top
PR528  -  [R_0402]  154.79 173.65 90 top
PR529  -  [R_0402]  155.62 170.75 180 bottom
PR531  -  [R_0402]  152.63 164.22 270 top
PR533  -  [R_0402]  148.54 173.04 0 top
PR534  -  [R_0603]  162.09 166.94 180 top
PR535  -  [R_0603]  157.81 160.5 270 bottom
PR536  -  [R_0402]  148.57 171.16 90 top
PR537  -  [R_0402]  150.34 169.69 270 bottom
PR539  -  [R_0603]  156.46 159.11 90 bottom
PR541  -  [R_0402]  150.44 172.91 0 top
PR542  -  [R_1206]  191.11 158.24 90 bottom
PR543  -  [R_0402]  149.45 174 270 bottom
PR544  -  [R_0402]  158.88 159.35 90 bottom
PR545  -  [R_0402]  150.39 167.83 0 bottom
PR546  -  [R_0402]  156.18 162.67 90 bottom
PR547  -  [R_0402]  155.29 162.67 90 bottom
PR548  -  [R0402_0OHM]  149.45 166.89 270 bottom
PR549  -  [R_0603]  155.04 162.81 90 top
PR550  -  [R_0402]  150.39 166.94 0 bottom
PR551  -  [R_0402]  150.39 166.05 0 bottom
PR552  -  [R_0603]  153.9 161.67 270 bottom
PR553  -  [R_0603]  152.63 160.27 90 bottom
PR554  -  [R_1206]  165.28 157.49 90 top
PR555  -  [R_0402]  155.04 160.52 90 bottom
PR556  -  [R_0402]  152.63 162.67 90 bottom
PR557  -  [R_0402]  153.52 162.67 90 bottom
PR558  -  [R_0402]  150.39 168.21 0 top
PR700  -  [R0402_0OHM]  9.37 63.11 90 top
PR701  -  [R_1206_4P-D]  5.82 63.91 270 top
PR702  -  [R0402_0OHM]  48.25 41.95 0 top
PR703  -  [R0402_0OHM]  28.27 68.64 0 top
PR704  -  [R_0402]  233.15 31.51 270 bottom
PR705  -  [R0402_0OHM]  232.26 31.51 270 bottom
PR706  -  [R_0402]  50.56 42.08 0 top
PR707  -  [R_0402]  34.01 64.58 270 top
PR708  -  [R_0402]  50.56 43.09 0 top
PR709  -  [R_0402]  126.83 129.4 0 top
PR710  -  [R0402_0OHM]  34.85 63.69 0 top
PR711  -  [R0402_0OHM]  34.9 64.58 0 top
PR712  -  [R_0402]  126.21 134.77 180 top
PR713  -  [R_0402]  125 128.47 180 top
PR714  -  [R0402_0OHM]  128.5 132.83 90 top
PR715  -  [R_0402]  126.73 128.47 180 top
PR716  -  [R_0402]  233.48 24.27 0 bottom
PR717  -  [R_0402]  257.11 16.23 180 bottom
PR718  -  [R0402_0OHM]  252.55 18.85 90 bottom
PR723  -  [R_1206_4P-D]  203.06 15.46 180 bottom
PR724  -  [R_1206]  214.45 21.29 0 bottom
PR732  -  [R_0402]  232.26 33.8 270 bottom
PR734  -  [R_0402]  239.16 18.68 90 bottom
PR735  -  [R_0402]  228.4 18.61 180 bottom
PR736  -  [R_0402]  239.11 14.49 90 bottom
PR737  -  [R_0402]  239.11 17.18 270 bottom
PR738  -  [R_0402]  238.29 18.68 90 bottom
PR739  -  [R0402_0OHM]  242.29 20.43 90 bottom
PR740  -  [R_0402]  232.33 23.31 180 bottom
PR741  -  [R_0402]  227.48 14.92 0 bottom
PR742  -  [R0402_0OHM]  240.04 18.68 90 bottom
PR743  -  [R_0402]  234.11 23.31 180 bottom
PR744  -  [R_0402]  238.24 15.41 270 bottom
PR745  -  [R_0402]  237.36 16.27 90 bottom
PR746  -  [R_0402]  237.37 19.6 270 bottom
PR747  -  [R_0402]  228.4 15.81 180 bottom
PR748  -  [R_0402]  228.4 16.7 180 bottom
PR749  -  [R_0402]  243.99 21.65 0 bottom
PR757  -  [R_0402]  232.33 24.83 180 bottom
PR758  -  [R_0402]  231.42 27.62 0 bottom
PR759  -  [R_0603]  226.56 25.16 270 bottom
PR760  -  [R_0402]  231.42 26.61 0 bottom
PR761  -  [R_0603]  227.85 25.14 270 bottom
PR762  -  [R_0402]  233.15 33.8 270 bottom
PR763  -  [R0402_0OHM]  231.42 29.53 0 bottom
PR764  -  [R_0402]  232.33 25.72 180 bottom
PR765  -  [R_0603]  223.17 27.85 180 bottom
PR766  -  [R0402_0OHM]  231.42 28.51 0 bottom
PR771  -  [R_0402]  256.2 14.47 90 bottom
PR772  -  [R_0402]  257.09 14.47 90 bottom
PR775  -  [R_1206]  222.22 32.26 90 bottom
PR1001  -  [R_0402]  130.71 117.13 0 top
PR1002  -  [R0402_0OHM]  132.03 110.13 180 top
PR1003  -  [R_0402]  132.21 114.88 180 top
PR1004  -  [R0402_0OHM]  267.38 32.3 180 bottom
PR1005  -  [R_1206]  186.97 22.82 0 bottom
PR1006  -  [R0402_0OHM]  267.38 31.43 180 bottom
PR1007  -  [R0402_0OHM]  267.38 30.57 180 bottom
PR1008  -  [R0402_0OHM]  266.47 33.21 0 bottom
PR1009  -  [R0402_0OHM]  258.93 37.22 270 bottom
PR1010  -  [R0402_0OHM]  267.38 29.66 180 bottom
PR1011  -  [R_0805]  265.53 24.23 90 bottom
PR1012  -  [R0402_0OHM]  265.15 36.31 90 bottom
PR1013  -  [R_0402]  260.37 23.69 0 bottom
PR1014  -  [R0402_0OHM]  263.37 36.31 90 bottom
PR1015  -  [R0402_0OHM]  260.45 25.01 90 bottom
PR1016  -  [R0402_0OHM]  264.26 36.31 90 bottom
PR1017  -  [R0402_0OHM]  261.34 25.01 90 bottom
PR1018  -  [R_0402]  261.59 37.22 270 bottom
PR1019  -  [R0402_0OHM]  262.48 36.31 90 bottom
PR1020  -  [R0402_0OHM]  260.7 36.31 90 bottom
PR1021  -  [R0402_0OHM]  259.56 25.01 90 bottom
PR1022  -  [R0402_0OHM]  258.67 25.01 90 bottom
PR1023  -  [R0402_0OHM]  259.82 36.31 90 bottom
PR1024  -  [R_0402]  258.04 36.31 90 bottom
PR1025  -  [R0402_0OHM]  256.46 34.48 180 bottom
PR1026  -  [R_0402]  183.16 18.94 0 top
PR1027  -  [R0402_0OHM]  256.46 33.59 180 bottom
PR1028  -  [R_0402]  256.46 32.7 180 bottom
PR1029  -  [R0402_0OHM]  256.46 31.81 180 bottom
PR1030  -  [R_0402]  247.12 28.74 90 bottom
PR1031  -  [R_0402]  245.32 29.66 270 bottom
PR1032  -  [R_0402]  246.2 28.74 90 bottom
PR1033  -  [R0402_0OHM]  247 31.99 0 bottom
PR1070  -  [R0402_0OHM]  256.18 21.91 0 bottom
PR1071  -  [R_0402]  254.41 21.91 0 bottom
PR1072  -  [R_0402]  253.54 21.91 180 bottom
PR1073  -  [R_0402]  248.92 20.19 270 bottom
PR1081  -  [R_0402]  225.09 51.88 180 bottom
PR1083  -  [R_0402]  225.09 50.99 180 bottom
PR1097  -  [R_0402]  175.18 25.97 180 top
PR1098  -  [R_0402]  173.07 30.11 270 top
PR1099  -  [R_0402]  176.25 28.46 270 top
PR1100  -  [R_0402]  240.5 32.36 270 bottom
PU1  -  [TS5A63157DCKR_SC70-6]  7.74 100.41 270 top
PU2  -  [LM393DR_SO8]  4.76 136.72 270 top
PU101  -  [TPS51225CRUKR_QFN20_3X3]  34.38 37.16 90 bottom
PU200  -  [RT8207MZQW_WQFN20_3X3]  149.17 24.01 0 bottom
PU300  -  [TPS51212DSCR_SON10_3X3]  38.09 66.75 0 bottom
PU400  -  [SY8033BDBC_DFN10_3X3]  105.8 29.87 180 bottom
PU500  -  [ISL95812HRZ-T_QFN32_4X4]  157.35 170.99 180 top
PU501  -  [ISL6208BCRZ-T_QFN8_2X2]  200.34 168.42 0 top
PU700  -  [BQ24737RGRR_VQFN20_3P5X3P5]  226.29 30.77 0 bottom
PU701  -  [INA199A1DCKR_SC70-6]  48.84 38.56 0 top
PU703  -  [LM393DR_SO8]  235.57 21.68 270 bottom
PU704  -  [TC7SH08FU_SSOP5]  245.98 21.25 0 bottom
PU1001  -  [CD3301RHHR_QFN36_6X6]  263.47 28.28 180 bottom
PU1080  -  [TC7SH08FU_SSOP5]  224.06 61.8 270 bottom
PU1081  -  [TC7SH08FU_SSOP5]  223.05 51.89 270 bottom
PWRSW1  -  [SHORTPADS]  278.74 92.77 0 top
Q4  -  [DMN65D8LW-7_SOT323-3]  40.99 137.73 0 bottom
Q5  -  [DMN65D8LW-7_SOT323-3]  46.64 139.76 90 bottom
Q14  -  [PMST3904_SOT323-3]  199.97 73.23 270 bottom
Q15  -  [PMST3904_SOT323-3]  196.72 154.63 180 bottom
Q16  -  [PMST3904_SOT323-3]  57.29 99.97 90 top
Q17  -  [PMST3904_SOT323-3]  182.8 45.1 90 top
Q21  -  [FDC654P-G_SSOT-6]  98.26 158.12 0 bottom
Q22  -  [DMN65D8LW-7_SOT323-3]  102.37 160.08 90 bottom
Q24  -  [DMG2301U-7_SOT23-3]  28.48 112.88 90 top
Q26  -  [PMST3904_SOT323-3]  188.21 121.38 270 top
Q27  -  [PMST3904_SOT323-3]  45.57 94.43 90 bottom
Q28  -  [PMST3904_SOT323-3]  248 55.91 0 bottom
Q29  -  [DMN66D0LDW-7_SOT363-6]  204.71 62.61 180 bottom
Q45  -  [DMN65D8LW-7_SOT323-3]  34.52 83.56 180 bottom
Q47  -  [DMN65D8LW-7_SOT323-3]  254.61 43.18 180 bottom
Q52  -  [DMN65D8LW-7_SOT323-3]  256.57 48.96 90 bottom
Q55  -  [DMN65D8LW-7_SOT323-3]  291.82 61.34 0 bottom
Q63  -  [SI4164DY-T1-GE3_SO8]  48.61 60.62 0 bottom
Q70  -  [DMN65D8LW-7_SOT323-3]  46.96 77.35 180 top
Q74  -  [DMN66D0LDW-7_SOT363-6]  32.17 84.63 90 top
Q75  -  [PDTA114EU_SC70-3]  27.23 85.27 90 top
Q77  -  [DMN65D8LW-7_SOT323-3]  258.29 44.07 180 bottom
Q78  -  [DMN65D8LW-7_SOT323-3]  131.8 168.15 0 top
Q79  -  [PDTA114EU_SC70-3]  132.56 169.99 270 top
Q80  -  [PDTA114EU_SC70-3]  23.71 76.52 90 top
Q81  -  [DMN66D0LDW-7_SOT363-6]  30.06 22.86 0 top
Q84  -  [DMN66D0LDW-7_SOT363-6]  285.95 87.84 0 top
Q86  -  [PDTA114EU_SC70-3]  29.96 82.74 90 top
Q87  -  [DMN65D8LW-7_SOT323-3]  15.98 133.09 0 top
Q89  -  [DMN65D8LW-7_SOT323-3]  135.42 167.32 90 top
Q90  -  [DMG2301U-7_SOT23-3]  264.51 78.4 180 bottom
Q93  -  [DMN65D8LW-7_SOT323-3]  24.16 73.98 270 top
Q110  -  [DMN66D0LDW-7_SOT363-6]  68.79 112.14 0 bottom
Q113  -  [DMN66D0LDW-7_SOT363-6]  72.35 112.14 0 bottom
Q115  -  [PMST3904_SOT323-3]  230.51 44.86 90 bottom
Q124  -  [DMN66D0LDW-7_SOT363-6]  128.81 165.4 90 top
Q186  -  [SI4835DDY-T1-E3_SO8]  15.11 139.26 270 top
Q295  -  [DMN66D0LDW-7_SOT363-6]  48.6 141.98 0 bottom
Q304  -  [DMN66D0LDW-7_SOT363-6]  41.44 72.69 90 top
Q318  -  [DMN66D0LDW-7_SOT363-6]  291 105.59 90 bottom
Q321  -  [DMN65D8LW-7_SOT323-3]  33.76 81.41 180 top
Q325  -  [DMN66D0LDW-7_SOT363-6]  101.64 99.9 270 top
Q326  -  [DMN65D8LW-7_SOT323-3]  26.07 146.37 270 top
Q327  -  [L2N7002WT1G_SC-70-3]  101.64 101.92 90 top
Q335  -  [DMN66D0LDW-7_SOT363-6]  19.77 149.23 0 top
Q336  -  [DMN66D0LDW-7_SOT363-6]  17.23 149.23 0 top
Q337  -  [DMN66D0LDW-7_SOT363-6]  18.25 145.16 0 top
Q338  -  [DMN65D8LW-7_SOT323-3]  277.34 80.27 180 bottom
Q339  -  [DMN66D0LDW-7_SOT363-6]  289.8 61.34 180 bottom
Q340  -  [DMN66D0LDW-7_SOT363-6]  287.26 61.34 180 bottom
Q343  -  [DMN66D0LDW-7_SOT363-6]  41.74 107.95 0 bottom
Q347  -  [DMN66D0LDW-7_SOT363-6]  44.28 107.95 0 bottom
QC1  -  [L2N7002WT1G_SC-70-3]  205.4 107.76 90 top
QC2  -  [DMN65D8LW-7_SOT323-3]  208.57 110.55 270 top
QC5  -  [DMN65D8LW-7_SOT323-3]  88.3 50.1 270 top
QC6  -  [LBSS138LT1G_SOT23-3]  166.6 148.88 180 bottom
QD6  -  [DMN66D0LDW-7_SOT363-6]  169.08 45.67 270 top
QD7  -  [L2N7002WT1G_SC-70-3]  146.4 84.07 0 top
QD9  -  [L2N7002WT1G_SC-70-3]  206.92 89.98 90 top
QH3  -  [L2N7002WT1G_SC-70-3]  56.87 68.9 180 top
QH4  -  [DMN66D0LDW-7_SOT363-6]  36.62 84.12 90 bottom
QH5  -  [BSS138_NL_SOT23-3]  55.08 79.07 90 bottom
R1  -  [R_0402]  51.87 140.65 180 bottom
R2  -  [R_0402]  51.87 141.54 180 bottom
R3  -  [R_0402]  80.75 148.73 270 top
R4  -  [R_0402]  43.66 140.7 90 bottom
R5  -  [R_0402]  81.76 148.73 270 top
R6  -  [R_0402]  101.22 141.75 90 bottom
R7  -  [R_0402]  114.73 69.41 180 bottom
R8  -  [R_0402]  114.73 68.14 180 bottom
R9  -  [R_0402]  114.73 65.09 180 bottom
R10  -  [R_0402]  42.65 140.7 90 bottom
R11  -  [R_0402]  38.07 145.3 270 bottom
R12  -  [R_0402]  275.69 66.79 90 bottom
R14  -  [R_0402]  116.94 130.54 90 top
R15  -  [R_0402]  271.12 81.17 270 bottom
R16  -  [R_0402]  270.1 81.17 270 bottom
R17  -  [R_0402]  246.15 72.07 0 bottom
R18  -  [R_0402]  269.09 81.17 270 bottom
R19  -  [R_0402]  110.59 130.42 90 top
R21  -  [R_0402]  273.15 81.17 270 bottom
R22  -  [R_0402]  274.67 66.79 90 bottom
R23  -  [R_0402]  273.66 66.79 90 bottom
R24  -  [R_0402]  272.64 66.79 90 bottom
R25  -  [R_0402]  271.63 66.79 90 bottom
R37  -  [R_0402]  113.77 131.33 270 top
R38  -  [R_0402]  111.48 131.33 270 top
R39  -  [R_0402]  182.85 30.72 90 bottom
R40  -  [R_0402]  184.89 30.72 90 bottom
R41  -  [R_0402]  183.87 30.72 90 bottom
R42  -  [R_0402]  185.39 43.96 270 bottom
R43  -  [R_0402]  10.08 149.42 180 top
R44  -  [R_0402]  10.08 150.31 180 top
R45  -  [R_0402]  10.97 150.33 270 top
R46  -  [R_0402]  184.38 43.96 270 bottom
R47  -  [R_0402]  85.06 166.74 90 top
R48  -  [R_0402]  91.67 166.75 90 top
R49  -  [R_0402]  10.08 148.25 180 top
R50  -  [R_0402]  89.46 166.69 180 top
R51  -  [R_0402]  109.32 125.62 270 top
R52  -  [R_0402]  86.38 166.69 0 top
R53  -  [R_0402]  81.38 161.74 0 bottom
R54  -  [R_0402]  85.44 161.99 180 bottom
R55  -  [R_0402]  89.76 161.99 0 bottom
R56  -  [R_0402]  289.15 81.04 270 bottom
R57  -  [R_0402]  22.63 159.45 0 top
R58  -  [R_0402]  30.2 148.07 90 top
R59  -  [R_0402]  290.3 81.04 270 bottom
R60  -  [R_0402]  123.67 136.64 90 top
R61  -  [R_0402]  24.61 148.07 90 top
R62  -  [R_0402]  278.41 75.76 0 bottom
R63  -  [R_0402]  29.31 148.07 90 top
R64  -  [R_0402]  25.5 148.07 90 top
R65  -  [R_0402]  22.63 160.34 0 top
R66  -  [R_0402]  36.37 149.92 180 top
R67  -  [R_0402]  22.63 161.23 0 top
R68  -  [R_0402]  36.37 150.81 180 top
R69  -  [R_0402]  35.28 160.01 90 top
R70  -  [R_0402]  34.39 160.01 90 top
R71  -  [R_0402]  22.63 158.56 0 top
R72  -  [R_0402]  22.12 157.67 0 top
R73  -  [R_0402]  22.12 156.78 0 top
R74  -  [R_0402]  26.14 160.8 270 top
R75  -  [R_0402]  278.41 74.23 0 bottom
R76  -  [R_0402]  278.41 72.33 0 bottom
R77  -  [R_0402]  279.32 73.22 180 bottom
R78  -  [R_0402]  287.25 67.55 90 bottom
R79  -  [R_0402]  288.14 68.47 270 bottom
R80  -  [R_0402]  278.41 71.44 0 bottom
R81  -  [R_0402]  279.32 70.55 180 bottom
R82  -  [R_0402]  182.85 32.5 90 bottom
R83  -  [R_0402]  181.01 42.16 270 bottom
R84  -  [R_0402]  185.95 32.5 90 bottom
R85  -  [R_0402]  181.98 42.16 270 bottom
R86  -  [R_0402]  183.87 32.5 90 bottom
R87  -  [R_0402]  184.38 42.18 270 bottom
R88  -  [R_0402]  185.39 42.18 270 bottom
R89  -  [R_0402]  184.89 32.5 90 bottom
R90  -  [R_0402]  186.87 32.5 90 bottom
R94  -  [R_0402]  266.93 79.39 270 bottom
R96  -  [R_0402]  30.25 117.03 0 bottom
R97  -  [R_0402]  91.11 105.09 180 bottom
R98  -  [R_0402]  30.33 113.42 270 bottom
R99  -  [R_0402]  33.88 128.38 90 bottom
R100  -  [R_0402]  130.1 148.02 180 bottom
R101  -  [R_0402]  130.1 141.29 180 bottom
R102  -  [R_0402]  229.39 66.61 0 bottom
R103  -  [R_0402]  270.1 78.47 90 bottom
R104  -  [R_0402]  273.66 69.48 270 bottom
R105  -  [R_0402]  269.09 78.47 90 bottom
R106  -  [R_0402]  272.64 69.48 270 bottom
R107  -  [R_0402]  271.12 78.47 90 bottom
R108  -  [R_0402]  274.67 69.48 270 bottom
R115  -  [R_0402]  31.22 113.42 270 bottom
R116  -  [R_0402]  33.88 127.39 270 bottom
R117  -  [R_0402]  35.99 130.37 180 bottom
R118  -  [R_0402]  35.91 128.38 90 bottom
R119  -  [R_0402]  32.87 128.38 90 bottom
R120  -  [R_0402]  31.85 128.38 90 bottom
R121  -  [R_0402]  32.87 127.39 270 bottom
R122  -  [R_0402]  31.85 127.39 270 bottom
R123  -  [R_0402]  34.82 127.32 0 bottom
R124  -  [R_0402]  34.9 128.38 90 bottom
R125  -  [R_0402]  91.11 106.36 180 bottom
R126  -  [R_0402]  37.01 113.35 180 bottom
R127  -  [R_0402]  143.23 152.51 90 top
R128  -  [R_0402]  37.87 113.35 0 bottom
R129  -  [R_0402]  41.63 108.95 90 bottom
R130  -  [R_0402]  32.87 98.18 270 bottom
R131  -  [R_0402]  40.44 90.74 180 bottom
R132  -  [R_0402]  42.52 108.95 90 bottom
R134  -  [R_0402]  231.67 49.09 0 bottom
R135  -  [R_0402]  115.92 134.35 90 top
R159  -  [R_0402]  89.64 159.28 270 bottom
R160  -  [R_0402]  90.5 155.84 270 bottom
R207  -  [R_0603]  97.18 166.56 90 bottom
R208  -  [R0603_0OHM]  130.02 150.62 90 top
R209  -  [R0603_0OHM]  114.91 89.6 0 bottom
R213  -  [R_0603]  13.24 86.17 0 bottom
R221  -  [R0402_0OHM]  111.91 31.81 0 top
R222  -  [R_0402]  120.12 150.74 90 top
R301  -  [R_0402]  109.75 174.56 0 top
R336  -  [R_0402]  111.25 150.71 90 top
R339  -  [R_0402]  108.58 150.71 90 top
R340  -  [R_0402]  120.29 168.59 0 top
R385  -  [R_0402]  29.36 90.87 0 bottom
R386  -  [R_0402]  29.36 89.98 0 bottom
R388  -  [R_0402]  38.45 87.62 90 bottom
R389  -  [R_0402]  29.36 94.43 0 bottom
R390  -  [R_0402]  33.76 97.27 90 bottom
R391  -  [R_0402]  29.36 93.54 0 bottom
R393  -  [R_0402]  39.52 89.85 0 bottom
R396  -  [R_0402]  248.59 54.93 180 bottom
R397  -  [R_0402]  229.92 41.4 0 bottom
R399  -  [R_0402]  248.46 58.74 180 bottom
R400  -  [R_0402]  226.44 42.63 90 bottom
R401  -  [R_0402]  227.33 42.63 90 bottom
R403  -  [R_0402]  14.15 83.76 180 bottom
R404  -  [R_0402]  30.28 95.31 180 bottom
R405  -  [R_0402]  14.15 82.74 180 bottom
R406  -  [R_0402]  30.28 92.65 180 bottom
R407  -  [R_0402]  234.62 80.58 180 bottom
R408  -  [R_0402]  234.62 81.6 180 bottom
R409  -  [R_0402]  15.01 83.76 0 bottom
R411  -  [R_0402]  30.28 91.76 180 bottom
R415  -  [R_0402]  291.18 67.55 90 bottom
R418  -  [R_0402]  233.09 43.24 180 bottom
R420  -  [R_0402]  234.48 43.24 0 bottom
R421  -  [R_0402]  97.13 100.19 90 bottom
R422  -  [R_0402]  106.59 160.33 180 bottom
R423  -  [R_0402]  104.81 160.33 180 bottom
R424  -  [R_0402]  39.52 91.63 0 bottom
R425  -  [R_0402]  235.56 54.09 90 bottom
R426  -  [R_0402]  14.02 124.78 180 top
R427  -  [R_0402]  31.23 126.59 180 top
R428  -  [R_0402]  31.23 127.61 180 top
R429  -  [R_0402]  31.14 114.41 180 top
R430  -  [R_0402]  31.14 115.42 180 top
R431  -  [R_0402]  39.52 95.57 0 bottom
R432  -  [R_0402]  240.89 56.38 90 bottom
R433  -  [R0402_0OHM]  94.46 161.66 90 bottom
R451  -  [R_0402]  35.66 163.31 90 top
R452  -  [R_0402]  36.68 163.31 90 top
R453  -  [R_0402]  32.1 163.31 90 top
R454  -  [R_0402]  33.12 163.31 90 top
R455  -  [R_0402]  28.55 163.31 90 top
R456  -  [R_0402]  29.56 163.31 90 top
R458  -  [R_0402]  26.26 163.31 90 top
R459  -  [R_0402]  25.25 163.31 90 top
R460  -  [R_0402]  40.23 163.31 90 top
R461  -  [R_0402]  39.34 163.31 90 top
R491  -  [R_0402]  22.5 150.18 0 top
R492  -  [R_0402]  81.76 131.97 270 bottom
R493  -  [R_0402]  32.61 160.92 270 top
R501  -  [R_0402]  180.9 41.09 180 top
R502  -  [R_0402]  177.27 38.09 90 top
R503  -  [R_0402]  176.76 45.61 270 top
R504  -  [R_0402]  63.53 74.68 315 top
R506  -  [R_0402]  202.32 61.05 90 bottom
R513  -  [R_0402]  203.86 65.6 0 bottom
R514  -  [R_0402]  31.6 33.07 0 top
R515  -  [R_0402]  32.37 23.79 270 top
R518  -  [R_0402]  26.39 148.07 90 top
R519  -  [R_0402]  118.34 137.55 270 top
R520  -  [R_0402]  28.65 23.1 270 top
R545  -  [R_0402]  105.36 90.49 0 top
R546  -  [R_0402]  105.36 89.6 0 top
R549  -  [R_0402]  117.91 89.6 180 top
R550  -  [R_0805]  126.97 139.64 180 top
R553  -  [R_0402]  117.91 90.62 180 top
R554  -  [R_0402]  117.91 87.57 180 top
R555  -  [R0402_0OHM]  120.19 89.73 180 top
R556  -  [R0402_0OHM]  120.19 87.69 180 top
R557  -  [R_0402]  119.28 88.71 0 top
R558  -  [R0402_0OHM]  119.28 90.74 0 top
R559  -  [R_0402]  116.99 88.58 0 top
R561  -  [R_0402]  106.73 92.27 180 top
R562  -  [R_0402]  116.18 95.24 90 top
R571  -  [R_0402]  46.46 157.49 270 top
R572  -  [R_0402]  54.08 157.49 270 top
R573  -  [R_0402]  47.73 157.49 270 top
R574  -  [R_0402]  55.35 157.49 270 top
R575  -  [R0402_0OHM]  57.89 156.58 90 top
R576  -  [R0402_0OHM]  56.62 156.58 90 top
R577  -  [R0402_0OHM]  52.81 156.58 90 top
R578  -  [R0402_0OHM]  51.54 156.58 90 top
R585  -  [R_0402]  111.91 34.1 0 top
R589  -  [R_0402]  111.91 34.99 0 top
R657  -  [R_0402]  258.22 60.26 0 bottom
R694  -  [R_0402]  296.9 110 270 bottom
R695  -  [R_0402]  125.7 156.32 90 bottom
R696  -  [R_0402]  134.09 170.96 270 bottom
R697  -  [R_0402]  121.26 156.32 90 bottom
R705  -  [R_0402]  126.9 167.83 0 top
R706  -  [R_0402]  115.54 156.45 90 bottom
R709  -  [R0402_0OHM]  133.2 170.96 270 bottom
R717  -  [R_0402]  103.5 163.51 0 top
R718  -  [R_0402]  129.77 165.34 90 top
R719  -  [R_0402]  259.13 45.44 180 bottom
R720  -  [R_0402]  272.9 36.51 0 bottom
R721  -  [R_0402]  45.57 109.87 270 bottom
R722  -  [R_0402]  40.61 106.03 90 bottom
R725  -  [R_0402]  125.7 155.46 270 bottom
R726  -  [R_0402]  133.5 165.55 0 top
R727  -  [R_0402]  132.89 171.64 180 top
R728  -  [R_0402]  118.72 157.24 270 bottom
R733  -  [R_0402]  53.57 16.14 270 bottom
R736  -  [R_0402]  15.85 161.53 90 top
R739  -  [R_0402]  13.05 141.11 270 bottom
R741  -  [R0402_0OHM]  246.15 68.39 0 bottom
R742  -  [R_0402]  14.83 161.53 90 top
R743  -  [R_0402]  289.66 109.08 90 bottom
R744  -  [R_0402]  290.68 109.08 90 bottom
R745  -  [R_0402]  288.64 109.08 90 bottom
R746  -  [R_0402]  287.63 109.08 90 bottom
R747  -  [R_0402]  294.99 66.36 180 bottom
R748  -  [R_0402]  297.28 116.45 90 bottom
R749  -  [R_0402]  296.26 116.45 90 bottom
R750  -  [R_0402]  283.71 97.85 0 top
R751  -  [R_0402]  283.71 96.84 0 top
R752  -  [R_0402]  283.7 100.19 0 top
R753  -  [R_0402]  283.7 99.17 0 top
R754  -  [R_0402]  276.86 88.93 90 bottom
R755  -  [R_0402]  123.49 131.26 180 bottom
R756  -  [R_0402]  113.77 114.31 270 bottom
R757  -  [R_0402]  92.18 114.31 270 bottom
R758  -  [R_0402]  121 136.64 90 top
R759  -  [R_0402]  254.43 51.88 180 bottom
R760  -  [R_0402]  255.67 45.02 0 bottom
R761  -  [R0402_0OHM]  243.56 78.25 270 bottom
R762  -  [R0402_0OHM]  38.87 68.66 0 top
R763  -  [R_0402]  236.07 78.25 270 bottom
R764  -  [R_0402]  278.13 88.93 90 bottom
R765  -  [R_0402]  230.81 61.41 180 bottom
R768  -  [R_0402]  229.39 65.72 0 bottom
R772  -  [R_0402]  236.83 80.53 270 bottom
R773  -  [R_0402]  273.15 78.47 90 bottom
